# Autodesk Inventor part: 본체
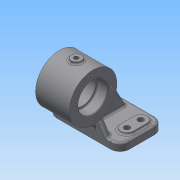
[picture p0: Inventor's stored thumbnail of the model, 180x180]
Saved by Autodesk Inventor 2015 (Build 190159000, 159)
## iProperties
Created: 2023-08
Part Number: 본체
Material: 일반
Document SubType Name: Modeling
Designer: 학생용
Density: 1 g/cm^3
Appearance: 기본값
Author: 학생용
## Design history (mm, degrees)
sketch "스케치1"
  geometry: L1 (-58, 12)-(58, 12); L2 (58, 12)-(58, 0); L3 (58, 0)-(-58, 0); L4 (-58, 0)-(-58, 12); 2 further points
  constraints: 8 end point, 2 parallel, 1 coincident, 1 horizontal, 1 midpoint, 1 perpendicular
  dimensions: "d0" = 116 distance of L2.end L3.end; "d1" = 12 distance of L1.end L2.end
extrude "돌출1" new body sketch "스케치1" stored distance "d2" = 70; taper "d3" = 0 deg
fillet "모깎기1" dims "d4" = 15
sketch "스케치2"
  geometry: L1 (84, 28)-(84, 50); L2 (94, 28)-(94, 50); L3 (74, 50)-(74, 28); L4 (43, 35)-(43, 87.935); L5 (2, 28)-(2, 50); L6 (-8, 28)-(-8, 50); L7 (12, 50)-(12, 28); L8 (0, 70)-(86, 70) reference; L9 (101, 15)-(101, 55) reference; A1 r 10 centre (84, 28) between (74, 28) and (94, 28); A2 r 10 centre (84, 50) between (94, 50) and (74, 50); A3 r 10 centre (2, 28) between (-8, 28) and (12, 28); A4 r 10 centre (2, 50) between (12, 50) and (-8, 50); 2 further points
  constraints: 18 end point, 8 point on circle, 6 symmetric about line, 4 centre point, 4 tangent, 2 vertical, 1 midpoint, 1 parallel, 2 other
  dimensions: "d6" = 20 distance between parallel lines of L3 L2; "d26" = 10 distance edge to line of A2 L8; "d28" = 22 distance of L1.start L1.end; "d73" = 82 distance of L1.end L5.end
extrude "돌출2" join sketch "스케치2" distance "d8" = 3; taper "d9" = 0 deg
sketch "스케치3"
  geometry: L1 (94, 28)-(94, 50) reference; L2 (74, 50)-(74, 28) reference; L3 (-8, 50)-(-8, 28) reference; L4 (12, 28)-(12, 50) reference; C1 r 4.5 at (84, 50); C2 r 4.5 at (84, 28); C3 r 4.5 at (2, 50); C4 r 4.5 at (2, 28); A1 r 10 centre (84, 50) between (94, 50) and (74, 50) reference; A2 r 10 centre (84, 28) between (74, 28) and (94, 28) reference; A3 r 10 centre (2, 28) between (-8, 28) and (12, 28) reference; A4 r 10 centre (2, 50) between (12, 50) and (-8, 50) reference; 1 further point
  constraints: 4 centre point, 4 coincident
  dimensions: "d10" = 9 diameter of C1; "d11" = 9 diameter of C2; "d12" = 9 diameter of C3; "d13" = 9 diameter of C4
extrude "돌출3" cut sketch "스케치3" stored distance "d14" = 3; taper "d15" = 0 deg
sketch "스케치4"
  geometry: L1 (12, 7)-(15, 7) reference; C1 r 38 at (70, 47); 1 further point
  constraints: 1 centre point
  dimensions: "d16" = 70 horizontal distance of point (0, 0) C1.centre; "d17" = 40 distance from line of C1.centre L1; "d18" = 76 diameter of C1
extrude "돌출4" join sketch "스케치4" stored distance "d19" = 54; taper "d20" = 0 deg
sketch "스케치5"
  geometry: L1 (-19.159, 37.933)-(-36, 12); L2 (-51, 12)-(-31, 12) reference; L3 (-58, 12)-(-58, 0) reference; L4 (0, 0)-(0, 51.675); L5 (19.159, 37.933)-(36, 12); L6 (-36, 12)-(36, 12); L7 (31, 12)-(51, 12) reference; L8 (-19.159, 37.933)-(19.159, 37.933)
  constraints: 10 end point, 2 symmetric about line, 1 collinear, 1 horizontal, 1 point on line, 1 vertical
  dimensions: "d21" = 33 deg angle of L3 L1; "d22" = 22 distance of L3.start L1.end; "d23" = 38.31786 distance of L1.start L5.start
extrude "돌출5" join sketch "스케치5" distance "d24" = 8; taper "d25" = 0 deg
sketch "스케치6"
  geometry: L1 (12, -27)-(87.882, 13.471); L2 (12, -35)-(0, -35) reference; L3 (12, -20)-(12, -35) reference; 2 further points
  constraints: 2 end point, 1 point on line, 3 other
  dimensions: "d77" = 8 distance from line of L2 L1.start
feature "리브1" sketch "스케치6" dims "d29" = 1, "d30" = 12, "d31" = 0, "d32" = 0, "d33" = 1, "d34" = 1
node "작업 평면2"
  node "작업 평면1"
sketch "스케치7"
  geometry: L1 (27, -38)-(27, 38) reference; L2 (27, 0)-(-27, 0); L3 (27, 0)-(27, 23.5); L4 (27, 23.5)-(10, 23.5); L5 (10, 23.5)-(10, 20.5); L6 (10, 20.5)-(-10, 20.5); L7 (-27, 38)-(-27, -38) reference; L8 (-27, 0)-(-27, 23.5); L9 (-27, 23.5)-(-10, 23.5); L10 (-10, 23.5)-(-10, 20.5); 1 further point
  constraints: 16 end point, 3 horizontal, 3 perpendicular, 2 point on line, 1 midpoint
  dimensions: "d36" = 47 diameter of L4 L2; "d37" = 41 diameter of L6 L2; "d38" = 17 distance of L3.end L4.end; "d40" = 17 distance of L8.end L9.end; "d41" = 47 diameter of L9 L2
revolve "회전1" sketch "스케치7" stored, may be unused: angle "d42" = 90 deg
sketch "스케치8" dims "d43" = 60
  geometry: C1 r 20.5 at (0, 0) reference; 6 further points
  constraints: 2 vertical alignment, 1 coincident, 7 other
  dimensions: "d46" = 360 deg dimension on C1.centre point (0, 30) (derived)
hole "구멍1" sketch "스케치8" at (0, 30), (-30, 0), (0, -30), (30, 0) diameter "d48" = 3.242; stored, may be unused: countersink angle "d52" = 90 deg, drill point angle "d54" = 120 deg; dims "d49" = 8, "d50" = 4, "d51" = 2, "d53" = 10
node "작업 평면3"
sketch "스케치9"
  geometry: L1 (27, 1.621)-(27, -1.621) reference; L2 (27, 0)-(-27, 0); L3 (-27, -1.621)-(-27, 1.621) reference; C1 r 8 at (0, 0); 2 further points
  constraints: 3 midpoint, 2 end point, 1 centre point, 1 coincident, 1 vertical alignment
  dimensions: "d55" = 16 diameter of C1
extrude "돌출6" join sketch "스케치9" distance "d56" = 3; taper "d58" = 0 deg; dims "d57" = 4, "d59" = 0
sketch "스케치10"
  geometry: C1 r 8 at (0, 0) reference; 2 further points
  constraints: 1 coincident
hole "구멍2" sketch "스케치10" at (0, 0) diameter "d60" = 5.188; stored, may be unused: countersink angle "d64" = 90 deg, drill point angle "d66" = 120 deg; dims "d61" = 25, "d62" = 7, "d63" = 4, "d65" = 30
chamfer "모따기1" distance "d67" = 1; stored, may be unused: second distance "d68" = 2, angle "d69" = 45 deg
fillet "모깎기2" dims "d70" = 1
fillet "모깎기3" dims "d71" = 3
fillet "모깎기4" dims "d72" = 3
sketch "스케치11"
  geometry: 2 further points
  constraints: 1 vertical alignment, 1 other
  dimensions: "d74" = 19 distance of point (0, 0) point (0, 19)
feature "엠보싱1" sketch "스케치11" dims "d0" = 116, "d1" = 12, "d6" = 20, "d26" = 10, "d28" = 22, "d73" = 82, "d75" = 0.5, "d76" = 0
node "솔리드1"
mirror "대칭1"
node "투영된 루프1"
node "투영된 루프2"
other parameters: "d35" = -38
